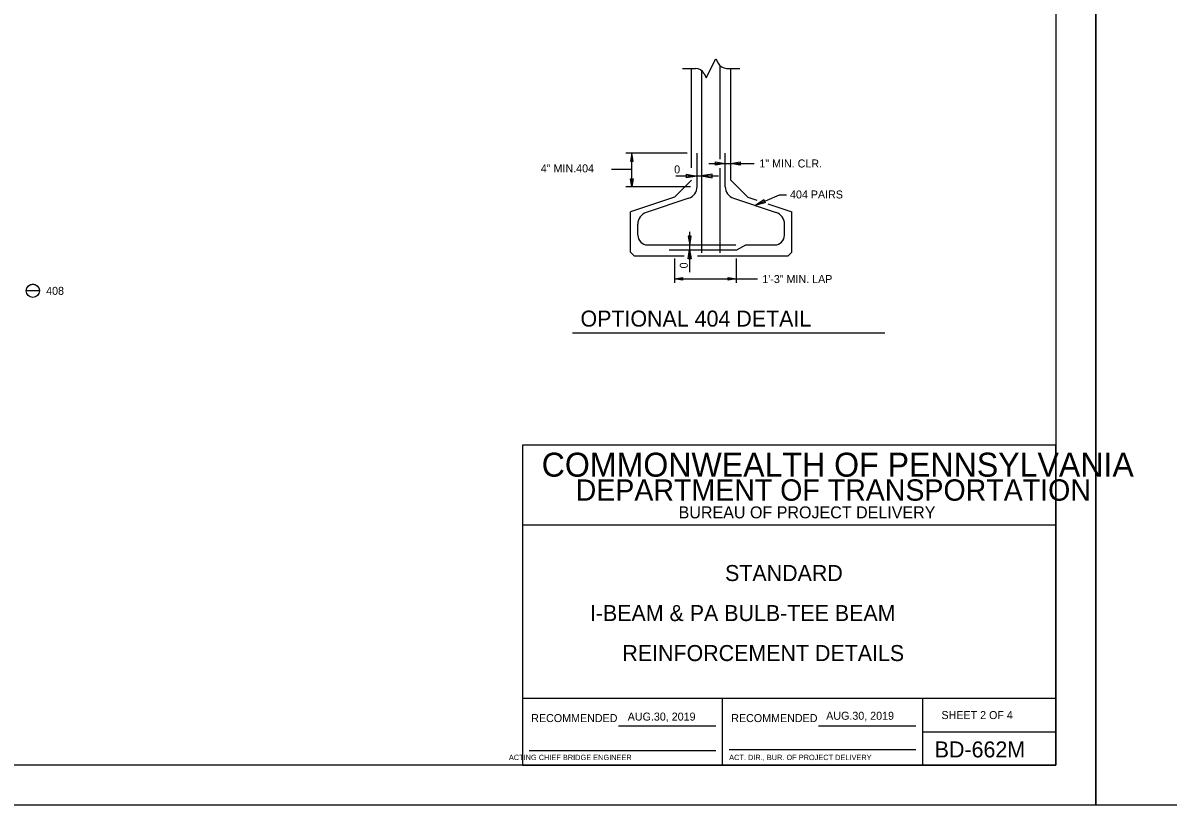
# Model space of a CAD drawing. Extents: x 637933 to 640019, y 298854 to 300042.
# Drawn here: x 638422.7 to 638852.1, y 298854.1 to 299147.4 of the extents above; entities that cross this region are included whole.
import ezdxf

# ---------------------------------------------------------------- set-up
doc = ezdxf.new("R2010")
doc.units = 0
for name, color, linetype in [('1', 7, 'Continuous'), ('3', 7, 'Continuous'), ('PLT-BNDY', 7, 'Continuous')]:
    doc.layers.add(name, color=color, linetype=linetype)

# ---------------------------------------------------------------- blocks, each defined once
blk = doc.blocks.new('SA')
at = {"layer": '3'}
blk.add_lwpolyline([(1.143, -0.1905), (1.143, 0.1905), (0, 0), (0, 0)], close=True, dxfattribs=at)

msp = doc.modelspace()

# ---------------------------------------------------------------- linework, layer by layer
at = {"layer": '1'}
for p, q in [((638809.94, 299433.12), (638809.94, 298869.12)), ((638684.17, 299096.23), (638684.17, 299131.22)), ((638673.4, 299093.01), (638673.4, 299130.33)), ((638677.29, 299061.16), (638677.29, 299129.41)), ((638688.06, 299088.43), (638688.06, 299130.33)), ((638671.77, 299098.56), (638648.77, 299098.56)), ((638650.97, 299085.97), (638650.97, 299098.56)), ((638675.46, 299085.97), (638675.46, 299098.56)), ((638686, 299085.97), (638686, 299098.56)), ((638686, 299094.45), (638686, 299096.56)), ((638643.31, 299092.5), (638650.97, 299092.5)), ((638679.87, 299094.68), (638686.52, 299094.68)), ((638684.17, 299061.16), (638684.17, 299092.95)), ((638685.93, 299094.68), (638688.05, 299094.68)), ((638688.05, 299094.68), (638696.86, 299094.68)), ((638673.4, 299088.43), (638666.98, 299082.01)), ((638683.5, 299089.96), (638667.43, 299089.96)), ((638688.06, 299088.43), (638694.48, 299082.01)), ((638673, 299085.97), (638648.77, 299085.97)), ((638666.98, 299082.01), (638650.48, 299076.52)), ((638672.33, 299081.62), (638656.37, 299076.3)), ((638689.14, 299081.62), (638705.1, 299076.3)), ((638694.48, 299082.01), (638697.87, 299080.89)), ((638697.12, 299078.96), (638706.33, 299082.92)), ((638701.97, 299079.52), (638710.98, 299076.52)), ((638706.33, 299082.92), (638708.94, 299082.92)), ((638650.48, 299061.39), (638650.48, 299076.52)), ((638710.98, 299061.39), (638710.98, 299076.52)), ((638653.23, 299067.79), (638653.23, 299071.95)), ((638708.23, 299067.79), (638708.23, 299071.95)), ((638672.67, 299069.08), (638672.67, 299053.89)), ((638656.9, 299064.12), (638689.99, 299064.12)), ((638664.95, 299062.27), (638690.36, 299062.27)), ((638690.36, 299062.27), (638693.73, 299064.12)), ((638693.73, 299064.12), (638704.56, 299064.12)), ((638650.48, 299061.39), (638651.86, 299060.02)), ((638651.86, 299060.02), (638670.59, 299060.02)), ((638666.98, 299059.05), (638666.98, 299049.94)), ((638675.64, 299060.02), (638709.6, 299060.02)), ((638690.11, 299059.05), (638690.11, 299049.94)), ((638710.98, 299061.39), (638709.6, 299060.02)), ((638666.98, 299051.44), (638690.11, 299051.44)), ((638690.11, 299051.44), (638698.07, 299051.44)), ((638428.9, 299046.93), (638423.94, 299046.93)), ((638745.86, 299031.07), (638628.79, 299031.07)), ((638809.94, 298989.12), (638609.94, 298989.12)), ((638609.94, 298989.12), (638609.94, 298869.12)), ((638809.94, 298869.12), (638809.94, 298989.12)), ((638809.94, 298959.12), (638609.94, 298959.12)), ((638809.94, 298894.12), (638609.94, 298894.12)), ((638684.94, 298869.12), (638684.94, 298894.12)), ((638759.94, 298894.12), (638759.94, 298869.12)), ((638646.02, 298883.83), (638682.44, 298883.83)), ((638721.02, 298883.83), (638757.44, 298883.83)), ((638759.94, 298881.62), (638809.94, 298881.62)), ((638612.44, 298874.62), (638682.44, 298874.62)), ((638687.44, 298874.99), (638757.44, 298874.99)), ((638809.94, 298869.12), (638023.93, 298869.12)), ((638609.94, 298869.12), (638809.94, 298869.12))]:
    msp.add_line(p, q, dxfattribs=at)
for points in [[(638678.11, 299128.34), (638678.92, 299126.73), (638682.52, 299133.93), (638683.32, 299132.32)], [(638669.93, 299130.33), (638674.89, 299130.33)], [(638686.54, 299130.33), (638691.53, 299130.33)], [(638423.94, 299046.93), (638423.96, 299047.21), (638424, 299047.48), (638424.07, 299047.73), (638424.17, 299047.98), (638424.31, 299048.24), (638424.47, 299048.46), (638424.66, 299048.67), (638424.91, 299048.89), (638425.17, 299049.07), (638425.41, 299049.19), (638425.59, 299049.27), (638425.86, 299049.35), (638426.22, 299049.4), (638426.47, 299049.41), (638426.84, 299049.37), (638427.15, 299049.3), (638427.43, 299049.2), (638427.69, 299049.06), (638427.9, 299048.92), (638428.14, 299048.72), (638428.33, 299048.51), (638428.51, 299048.26), (638428.65, 299048.02), (638428.73, 299047.82), (638428.83, 299047.51), (638428.88, 299047.2), (638428.9, 299046.93)]]:
    msp.add_lwpolyline(points, dxfattribs=at)
for points in [[(638650.47, 299095.56), (638651.47, 299095.56), (638650.97, 299098.56), (638650.97, 299098.56)], [(638682.42, 299095.28), (638686.02, 299094.68), (638682.42, 299094.08)], [(638691.65, 299094.08), (638688.05, 299094.68), (638691.65, 299095.28)], [(638650.47, 299088.97), (638651.47, 299088.97), (638650.97, 299085.97), (638650.97, 299085.97)], [(638701.02, 299079.92), (638697.12, 299078.96), (638700.5, 299081.14)], [(638669.98, 299050.94), (638666.98, 299051.44), (638669.98, 299051.94)], [(638687.11, 299051.94), (638690.11, 299051.44), (638687.11, 299050.94)]]:
    msp.add_lwpolyline(points, close=True, dxfattribs=at)
msp.add_circle((638426.42, 299046.93), 2.48, dxfattribs=at)
for centre, radius, start, end in [((638686.54, 299133.93), 3.6, 206.5651, 270), ((638674.89, 299126.73), 3.6, 26.5651, 90), ((638670.88, 299085.97), 4.58, 288.4349, 0), ((638690.58, 299085.97), 4.58, 180, 251.5651), ((638657.82, 299071.95), 4.58, 108.4349, 180), ((638703.65, 299071.95), 4.58, 0, 71.5651), ((638656.9, 299067.79), 3.67, 180, 270), ((638704.56, 299067.79), 3.67, 270, 0)]:
    msp.add_arc(centre, radius, start, end, dxfattribs=at)
at = {"layer": 'PLT-BNDY'}
for points in [[(637983.93, 299448.12), (638824.93, 299448.12), (638824.93, 298854.12), (637983.93, 298854.12)], [(638824.93, 299448.12), (639665.93, 299448.12), (639665.93, 298854.12), (638824.93, 298854.12)]]:
    msp.add_lwpolyline(points, close=True, dxfattribs=at)

# ---------------------------------------------------------------- block references
at = {"layer": '1'}
for p, xscale, yscale, rotation in [((638675.4, 299089.95), 3.4644972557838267, -3.4644972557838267, 180), ((638672.7, 299064.1), 2.8870810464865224, 2.887081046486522, 89.9999999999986), ((638672.67, 299062.26), 2.8870810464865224, -2.887081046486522, -90.00000000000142)]:
    msp.add_blockref('SA', p, dxfattribs=dict(at, xscale=xscale, yscale=yscale, rotation=rotation))
at = {"layer": '1', "xscale": 3.4644972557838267, "yscale": 3.4644972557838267}
msp.add_blockref('SA', (638677.09, 299090), dxfattribs=at)

# ---------------------------------------------------------------- texts
at = {"layer": '1'}
for s, rotation, p in [('4" MIN.404', 360, (638616.88, 299091.33)), ('0', 90, (638671.96, 299055.34))]:
    msp.add_text(s, height=3, rotation=rotation, dxfattribs=at).set_placement(p)
for s, height, p in [('0', 3, (638666.87, 299090.93)), ('1" MIN. CLR.', 2.9999, (638698.81, 299093.16)), ('404 PAIRS', 3, (638710.3, 299081.55)), ('1\'-3" MIN. LAP', 3, (638699.91, 299049.83)), ('408', 3, (638431.39, 299045.42)), ('OPTIONAL 404 DETAIL', 6, (638631.74, 299033.51)), ('COMMONWEALTH OF PENNSYLVANIA', 9, (638617.19, 298977.24)), ('DEPARTMENT OF TRANSPORTATION', 8.0003, (638629.94, 298968.24)), ('BUREAU OF PROJECT DELIVERY', 4.5, (638668.53, 298961.62)), ('STANDARD', 6, (638685.94, 298938.12)), ('I-BEAM & PA BULB-TEE BEAM', 6, (638635.26, 298923.12)), ('REINFORCEMENT DETAILS', 6, (638647.44, 298908.12)), ('RECOMMENDED', 3, (638613.27, 298885.24)), ('AUG.30, 2019', 3, (638649.45, 298885.8)), ('RECOMMENDED', 3, (638688.27, 298885.24)), ('AUG.30, 2019', 3, (638723.86, 298886.11)), ('SHEET 2 OF 4', 3, (638767.09, 298886.37)), ('BD-662M', 6, (638764.56, 298871.99)), ('       ACTING CHIEF BRIDGE ENGINEER', 2.0002, (638599.52, 298870.99)), ('ACT. DIR., BUR. OF PROJECT DELIVERY', 2.0002, (638687.48, 298870.99))]:
    msp.add_text(s, height=height, dxfattribs=at).set_placement(p)

doc.saveas('drawing.dxf')
